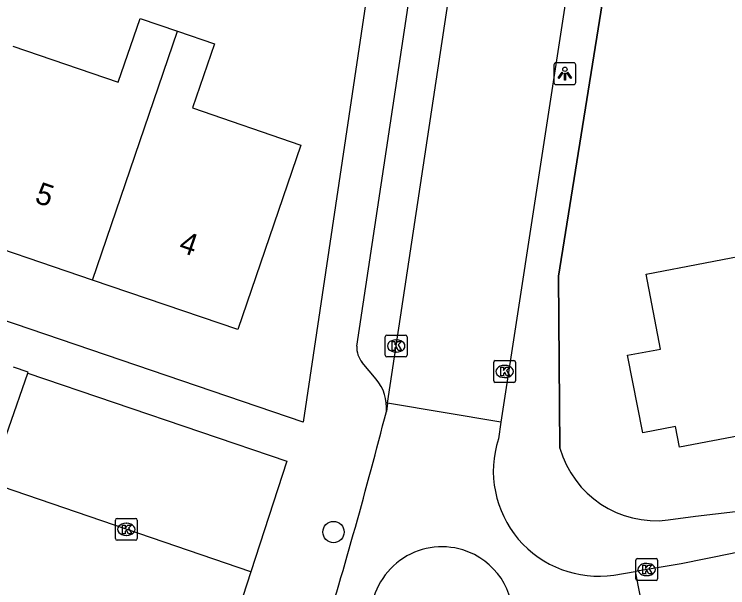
# Model space of a CAD drawing. Extents: x 162675 to 163482, y 379761 to 381227.
# Drawn here: x 163132.74 to 163165.45, y 380949.11 to 380975.42 of the extents above; entities that cross this region are included whole.
import ezdxf

# ---------------------------------------------------------------- set-up
doc = ezdxf.new("R2010")
doc.units = 0
for name, color, linetype in [('IMGEO_Berm_groen', 7, 'Continuous'), ('IMGEO_Boom', 7, 'Continuous'), ('IMGEO_Hek', 7, 'Continuous'), ('IMGEO_Kolk', 7, 'Continuous'), ('IMGEO_Lichtpunt', 7, 'Continuous'), ('IMGEO_Pand', 7, 'Continuous'), ('IMGEO_Pand_nummerreeks', 7, 'Continuous'), ('IMGEO_Rijbaan_lokaal_gesloten', 7, 'Continuous'), ('IMGEO_Rijbaan_lokaal_open', 7, 'Continuous'), ('IMGEO_Voetpad_open', 7, 'Continuous')]:
    doc.layers.add(name, color=color, linetype=linetype)

msp = doc.modelspace()

# ---------------------------------------------------------------- linework, layer by layer
at = {"layer": 'IMGEO_Berm_groen'}
for points in [[(163163.927, 381002.51), (163163.006, 380996.615), (163157.686, 380963.398), (163157.76, 380955.51)], [(163162.723, 380952.217), (163163.966, 380952.385), (163167.647, 380952.826)]]:
    msp.add_lwpolyline(points, dxfattribs=at)
msp.add_arc((163162.163, 380956.759), 4.577, 195.8393, 277.0313, dxfattribs=at)
at = {"layer": 'IMGEO_Boom'}
msp.add_circle((163147.375, 380951.664), 0.489, dxfattribs=at)
at = {"layer": 'IMGEO_Hek'}
msp.add_lwpolyline([(163157.76, 380955.51), (163157.686, 380963.398), (163163.006, 380996.615)], dxfattribs=at)
at = {"layer": 'IMGEO_Kolk'}
for p, q in [((163149.75, 380959.774), (163149.75, 380960.626)), ((163149.825, 380960.7), (163150.677, 380960.7)), ((163150.751, 380960.626), (163150.751, 380959.774)), ((163150.238, 380960.48), (163150.263, 380960.48)), ((163150.261, 380959.92), (163150.236, 380959.92)), ((163150.677, 380959.7), (163149.825, 380959.7)), ((163154.72, 380958.606), (163154.72, 380959.458)), ((163154.795, 380959.532), (163155.647, 380959.532)), ((163155.208, 380959.312), (163155.233, 380959.312)), ((163155.721, 380959.458), (163155.721, 380958.606)), ((163155.231, 380958.752), (163155.206, 380958.752)), ((163155.647, 380958.532), (163154.795, 380958.532)), ((163137.376, 380951.36), (163137.376, 380952.212)), ((163137.451, 380952.286), (163138.303, 380952.286)), ((163137.864, 380952.066), (163137.889, 380952.066)), ((163138.377, 380952.212), (163138.377, 380951.36)), ((163137.887, 380951.506), (163137.862, 380951.506)), ((163138.303, 380951.286), (163137.451, 380951.286)), ((163161.31, 380950.442), (163162.162, 380950.442)), ((163161.235, 380949.516), (163161.235, 380950.368)), ((163161.723, 380950.222), (163161.748, 380950.222)), ((163162.236, 380950.368), (163162.236, 380949.516)), ((163162.162, 380949.442), (163161.31, 380949.442)), ((163161.746, 380949.662), (163161.721, 380949.662))]:
    msp.add_line(p, q, dxfattribs=at)
for points in [[(163149.75, 380959.774), (163149.75, 380960.626)], [(163149.825, 380960.7), (163150.677, 380960.7)], [(163150.751, 380960.626), (163150.751, 380959.774)], [(163150.071, 380960.4), (163150.194, 380960.4), (163150.194, 380960.249), (163150.324, 380960.4), (163150.488, 380960.4), (163150.342, 380960.249), (163150.495, 380960), (163150.343, 380960), (163150.258, 380960.164), (163150.194, 380960.097), (163150.194, 380960), (163150.071, 380960), (163150.071, 380960.4)], [(163150.677, 380959.7), (163149.825, 380959.7)], [(163154.72, 380958.606), (163154.72, 380959.458)], [(163154.795, 380959.532), (163155.647, 380959.532)], [(163155.721, 380959.458), (163155.721, 380958.606)], [(163155.041, 380959.232), (163155.164, 380959.232), (163155.164, 380959.081), (163155.294, 380959.232), (163155.458, 380959.232), (163155.312, 380959.081), (163155.465, 380958.832), (163155.313, 380958.832), (163155.228, 380958.996), (163155.164, 380958.929), (163155.164, 380958.832), (163155.041, 380958.832), (163155.041, 380959.232)], [(163155.647, 380958.532), (163154.795, 380958.532)], [(163137.376, 380951.36), (163137.376, 380952.212)], [(163137.451, 380952.286), (163138.303, 380952.286)], [(163138.377, 380952.212), (163138.377, 380951.36)], [(163137.697, 380951.986), (163137.82, 380951.986), (163137.82, 380951.835), (163137.95, 380951.986), (163138.114, 380951.986), (163137.968, 380951.835), (163138.121, 380951.586), (163137.969, 380951.586), (163137.884, 380951.75), (163137.82, 380951.683), (163137.82, 380951.586), (163137.697, 380951.586), (163137.697, 380951.986)], [(163138.303, 380951.286), (163137.451, 380951.286)], [(163161.31, 380950.442), (163162.162, 380950.442)], [(163161.235, 380949.516), (163161.235, 380950.368)], [(163161.556, 380950.142), (163161.679, 380950.142), (163161.679, 380949.991), (163161.809, 380950.142), (163161.973, 380950.142), (163161.827, 380949.991), (163161.98, 380949.742), (163161.828, 380949.742), (163161.743, 380949.906), (163161.679, 380949.839), (163161.679, 380949.742), (163161.556, 380949.742), (163161.556, 380950.142)], [(163162.236, 380950.368), (163162.236, 380949.516)], [(163162.162, 380949.442), (163161.31, 380949.442)]]:
    msp.add_lwpolyline(points, dxfattribs=at)
for centre, start, end in [((163149.827, 380960.624), 91.552, 178.448), ((163149.827, 380960.624), 91.552, 178.448), ((163150.675, 380960.624), 1.552, 88.448), ((163150.675, 380960.624), 1.552, 88.448), ((163149.827, 380959.776), 181.552, 268.448), ((163149.827, 380959.776), 181.552, 268.448), ((163150.675, 380959.776), 271.552, 358.448), ((163150.675, 380959.776), 271.552, 358.448), ((163154.797, 380959.456), 91.552, 178.448), ((163154.797, 380959.456), 91.552, 178.448), ((163155.645, 380959.456), 1.552, 88.448), ((163155.645, 380959.456), 1.552, 88.448), ((163154.797, 380958.608), 181.552, 268.448), ((163154.797, 380958.608), 181.552, 268.448), ((163155.645, 380958.608), 271.552, 358.448), ((163155.645, 380958.608), 271.552, 358.448), ((163137.453, 380952.21), 91.552, 178.448), ((163137.453, 380952.21), 91.552, 178.448), ((163138.301, 380952.21), 1.552, 88.448), ((163138.301, 380952.21), 1.552, 88.448), ((163137.453, 380951.362), 181.552, 268.448), ((163137.453, 380951.362), 181.552, 268.448), ((163138.301, 380951.362), 271.552, 358.448), ((163138.301, 380951.362), 271.552, 358.448), ((163161.312, 380950.366), 91.552, 178.448), ((163161.312, 380950.366), 91.552, 178.448), ((163162.16, 380950.366), 1.552, 88.448), ((163162.16, 380950.366), 1.552, 88.448), ((163161.312, 380949.518), 181.552, 268.448), ((163161.312, 380949.518), 181.552, 268.448), ((163162.16, 380949.518), 271.552, 358.448), ((163162.16, 380949.518), 271.552, 358.448)]:
    msp.add_arc(centre, 0.0765, start, end, dxfattribs=at)
for centre, major_axis, ratio, start_param, end_param in [((163150.237, 380960.2), (-0.387, 0.002), 0.722429, 4.712389, 7.853982), ((163150.262, 380960.2), (-0.39, 0.002), 0.717154, 1.570796, 4.712389), ((163155.207, 380959.032), (-0.387, 0.002), 0.722429, 4.712389, 7.853982), ((163155.232, 380959.032), (-0.39, 0.002), 0.717154, 1.570796, 4.712389), ((163137.863, 380951.786), (-0.387, 0.002), 0.722429, 4.712389, 7.853982), ((163137.888, 380951.786), (-0.39, 0.002), 0.717154, 1.570796, 4.712389), ((163161.722, 380949.942), (-0.387, 0.002), 0.722429, 4.712389, 7.853982), ((163161.747, 380949.942), (-0.39, 0.002), 0.717154, 1.570796, 4.712389)]:
    msp.add_ellipse(centre, major_axis=major_axis, ratio=ratio, start_param=start_param, end_param=end_param, dxfattribs=at)
at = {"layer": 'IMGEO_Lichtpunt'}
for p, q in [((163157.484, 380973.101), (163157.484, 380972.294)), ((163157.484, 380973.101), (163157.484, 380972.294)), ((163158.386, 380973.196), (163157.578, 380973.196)), ((163158.386, 380973.196), (163157.578, 380973.196)), ((163158.48, 380972.294), (163158.48, 380973.101)), ((163158.48, 380972.294), (163158.48, 380973.101)), ((163157.578, 380972.2), (163158.386, 380972.2)), ((163157.578, 380972.2), (163158.386, 380972.2))]:
    msp.add_line(p, q, dxfattribs=at)
for points in [[(163157.858, 380972.765), (163157.897, 380972.737), (163157.709, 380972.475), (163157.671, 380972.502), (163157.858, 380972.765)], [(163157.96, 380972.717), (163158.007, 380972.717), (163158.007, 380972.395), (163157.96, 380972.395), (163157.96, 380972.717)], [(163158.07, 380972.737), (163158.108, 380972.764), (163158.295, 380972.502), (163158.256, 380972.474), (163158.07, 380972.737)]]:
    msp.add_lwpolyline(points, dxfattribs=at)
msp.add_circle((163157.983, 380972.899), 0.0994, dxfattribs=at)
for centre, start, end in [((163157.578, 380973.101), 90, 180), ((163157.578, 380973.101), 90, 180), ((163158.386, 380973.101), 0, 90), ((163158.386, 380973.101), 0, 90), ((163157.578, 380972.294), 180, 270), ((163157.578, 380972.294), 180, 270), ((163158.386, 380972.294), 270, 0), ((163158.386, 380972.294), 270, 360)]:
    msp.add_arc(centre, 0.0946, start, end, dxfattribs=at)
at = {"layer": 'IMGEO_Pand'}
for points in [[(163132.676, 380973.953), (163137.508, 380972.3), (163138.51, 380975.232), (163140.218, 380974.648)], [(163140.218, 380974.648), (163141.917, 380974.067), (163140.91, 380971.123), (163145.878, 380969.423), (163142.982, 380960.951), (163136.323, 380963.22)], [(163136.323, 380963.22), (163140.218, 380974.648)], [(163174.768, 380962.336), (163171.327, 380961.682), (163171.514, 380960.701), (163170.532, 380960.513), (163171.197, 380957.079), (163163.236, 380955.553), (163163.053, 380956.51), (163161.555, 380956.214), (163160.852, 380959.773), (163162.366, 380960.055), (163161.71, 380963.504), (163167.125, 380964.531), (163166.372, 380968.467), (163173.332, 380969.79), (163174.768, 380962.336)], [(163136.323, 380963.22), (163129.779, 380965.45)]]:
    msp.add_lwpolyline(points, dxfattribs=at)
at = {"layer": 'IMGEO_Rijbaan_lokaal_gesloten'}
for points in [[(163173.076, 380952.383), (163171.638, 380952.02), (163165.647, 380950.682), (163163.317, 380950.209), (163161.213, 380949.855)], [(163161.213, 380949.855), (163162.268, 380944.505)]]:
    msp.add_lwpolyline(points, dxfattribs=at)
at = {"layer": 'IMGEO_Rijbaan_lokaal_open'}
for points in [[(163162.27, 381003.774), (163161.692, 381000), (163155.052, 380956.709)], [(163149.856, 380957.574), (163155.712, 380996.349)], [(163149.856, 380957.574), (163149.799, 380957.195)], [(163155.052, 380956.709), (163149.856, 380957.574)], [(163155.052, 380956.709), (163154.933, 380955.935)], [(163143.584, 380949.834), (163131.602, 380953.931)], [(163143.584, 380949.834), (163140.631, 380940.742)], [(163160.235, 380949.691), (163161.213, 380949.855)]]:
    msp.add_lwpolyline(points, dxfattribs=at)
for centre, radius, start, end in [((162911.511, 381018.219), 245.978, 343.07514, 345.63555), ((163159.526, 380954.462), 4.823, 162.2144, 278.4571), ((163152.345, 380947.722), 3.264, 72.7733, 179.4744), ((163152.344, 380947.722), 3.264, 354.8991, 72.7599)]:
    msp.add_arc(centre, radius, start, end, dxfattribs=at)
at = {"layer": 'IMGEO_Voetpad_open'}
for points in [[(163148.443, 380960.2), (163153.526, 380993.879)], [(163149.106, 380977.626), (163145.977, 380956.699), (163111.192, 380968.563)], [(163149.332, 380958.672), (163148.697, 380959.44)], [(163131.602, 380953.931), (163133.359, 380958.954)], [(163133.359, 380958.954), (163133.374, 380958.997), (163132.702, 380959.224)], [(163133.359, 380958.954), (163145.235, 380954.922), (163143.584, 380949.834)]]:
    msp.add_lwpolyline(points, dxfattribs=at)
for centre, radius, start, end in [((163149.537, 380960.143), 1.096, 177.028, 219.9324), ((163147.817, 380957.381), 1.991, 354.6478, 40.4442)]:
    msp.add_arc(centre, radius, start, end, dxfattribs=at)

# ---------------------------------------------------------------- texts
at = {"layer": 'IMGEO_Pand_nummerreeks'}
for s, p in [('5', (163133.63, 380966.801)), ('4', (163140.233, 380964.551))]:
    msp.add_text(s, height=1, rotation=341.182, dxfattribs=at).set_placement(p)

doc.saveas('drawing.dxf')
